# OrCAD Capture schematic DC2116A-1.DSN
size Custom
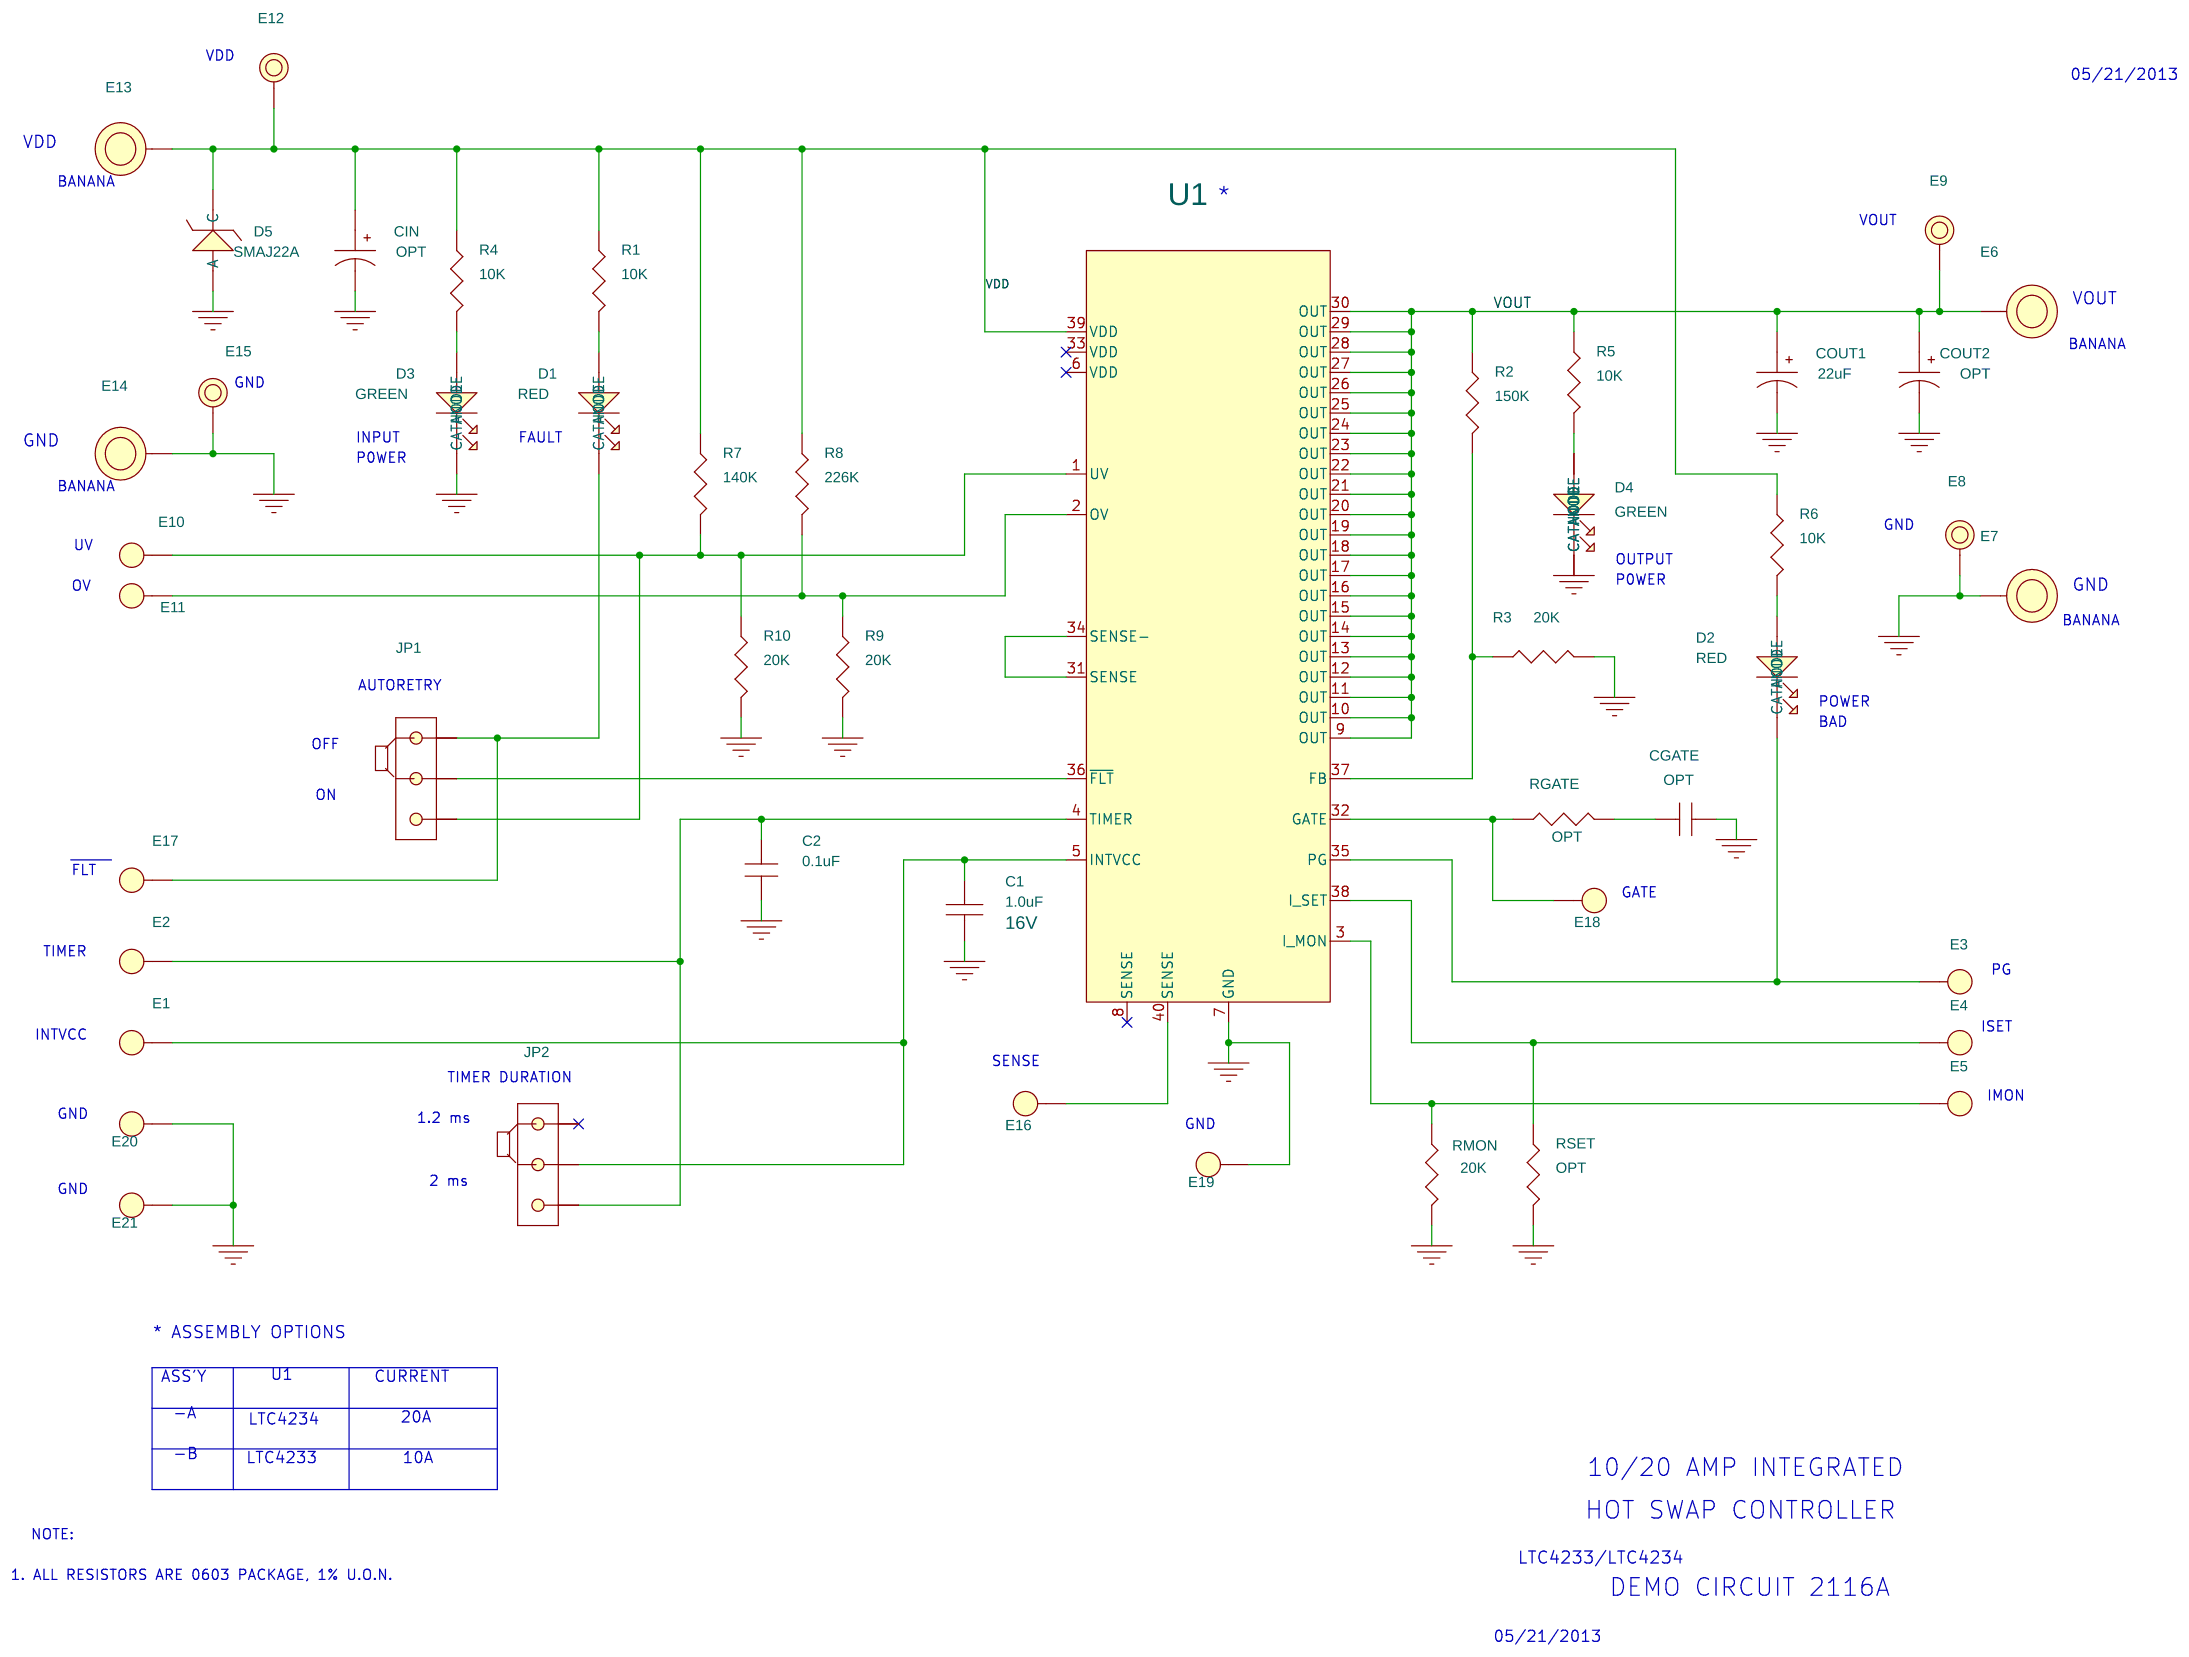
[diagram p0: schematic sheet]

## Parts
C1  1.0uF  [CC0603N]
C2  0.1uF  [CC0603N]
CGATE  OPT  [CC0603N]
CIN  OPT  [CAPTANT7343N]
COUT1  22uF  [CAPTANT7343N]
COUT2  OPT  [CAPTANT7343N]
D1  RED  [WURTH_LED_0805]
D2  RED  [WURTH_LED_0805]
D3  GREEN  [WURTH_LED_0805]
D4  GREEN  [WURTH_LED_0805]
D5  SMAJ22A  [DIODESINC-SMA]
E1  MILL-MAX 2308  [MILLMAX2308]
E2  MILL-MAX 2308  [MILLMAX2308]
E3  MILL-MAX 2308  [MILLMAX2308]
E4  MILL-MAX 2308  [MILLMAX2308]
E5  MILL-MAX 2308  [MILLMAX2308]
E6  BANANA, KEYSTONE-575-4  [KEY-575-4]
E7  BANANA, KEYSTONE-575-4  [KEY-575-4]
E8  MILL MAX 2501  [MILLMAX2501]
E9  MILL MAX 2501  [MILLMAX2501]
E10  MILL-MAX 2308  [MILLMAX2308]
E11  MILL-MAX 2308  [MILLMAX2308]
E12  MILL MAX 2501  [MILLMAX2501]
E13  BANANA, KEYSTONE-575-4  [KEY-575-4]
E14  BANANA, KEYSTONE-575-4  [KEY-575-4]
E15  MILL MAX 2501  [MILLMAX2501]
E16  MILL-MAX 2308  [MILLMAX2308]
E17  MILL-MAX 2308  [MILLMAX2308]
E18  MILL-MAX 2308  [MILLMAX2308]
E19  MILL-MAX 2308  [MILLMAX2308]
E20  MILL-MAX 2308  [MILLMAX2308]
E21  MILL-MAX 2308  [MILLMAX2308]
JP1  3 Pins 2mm Ctrs.  [JP3X1/079]
JP2  3 Pins 2mm Ctrs.  [JP3X1/079]
R1  10K  [CR0805N]
R2  150K  [CR0603N]
R3  20K  [CR0603N]
R4  10K  [CR0805N]
R5  10K  [CR0805N]
R6  10K  [CR0805N]
R7  140K  [CR0603N]
R8  226K  [CR0603N]
R9  20K  [CR0603N]
R10  20K  [CR0603N]
RGATE  OPT  [CR0603N]
RMON  20K  [CR0805N]
RSET  OPT  [CR0805N]
U1  LTC4234CWHH  [LTC-WHH]
XJP1  2mm Ctrs.
XJP2  2mm Ctrs.

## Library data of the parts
C1 = CAP: CAP., 1uF, X7R, 16V, 10%, 0603; CLASS: DISCRETE; Dielectric Type: X7R; Manufacturer: AVX; Manufacturer PN: 0603YC105KAT2A; PART_NUMBER: 150-3384; Package Size: 0603; Rated Voltage: 16V; Tolerance: 10%
C2 = 0.1uF_16V_10%_X7R_0603
CGATE = OPT_0603
CIN COUT2 = CAP_OPT_7343
COUT1 = 22uF_25V_10%_TANT._7343
D1 D2 = LED,RED,_0805,_WURTH
D3 D4 = LED,GREEN,_0805,_WURTH
D5 = DIODE,_TVS,_SMAJ22A,_SMA
E1-E5 E10 E11 E16-E21 = TEST_POINT,_.156,_MILL-MAX_2308
E6 E7 E13 E14 = BANANA,_KEYSTONE-575-4
E8 E9 E12 E15 = TESTPOINT,_.219,_MILL-_MAX_2501
JP1 JP2 = 3_PIN_HEADER_D_.079_SINGLE_ROW
R1 R4-R6 = 10K_5%_1_8W_0805
R2 = 150K_1%_1_10W_0603
R3 R9 R10 = 20K_1%_1_10W_0603
R7 = 140K_1%_1_10W_0603
R8 = 226K_1%_1_10W_0603
RGATE = OPT_0603_v2
RMON = 20K_1%_1_8W_0805
RSET = OPT_0805
U1 = LTC4234
XJP1 XJP2 = SHUNT,_2MM

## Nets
GND: C1.2 C2.2 CGATE.2 CIN.2 COUT1.2 COUT2.2 D3.1(CATHODE) D4.1(CATHODE) D5.2(A) E7.1 E8.1 E14.1 E15.1 E19.1(A) E20.1(A) E21.1(A) R3.2 R9.2 R10.2 RMON.2 RSET.2 U1.7(GND)
VDD: CIN.1 D5.1(C) E12.1 E13.1 R1.1 R4.1 R6.1 R7.1 R8.1 U1.39(VDD)
VOUT: COUT1.1 COUT2.1 E6.1 E9.1 R2.1 R5.1 U1.9(OUT) U1.10(OUT) U1.11(OUT) U1.12(OUT) U1.13(OUT) U1.14(OUT) U1.15(OUT) U1.16(OUT) U1.17(OUT) U1.18(OUT) U1.19(OUT) U1.20(OUT) U1.21(OUT) U1.22(OUT) U1.23(OUT) U1.24(OUT) U1.25(OUT) U1.26(OUT) U1.27(OUT) U1.28(OUT) U1.29(OUT) U1.30(OUT)
N17257135: E10.1(A) JP1.3 R7.2 R10.1 U1.1(UV)
N17258019: D1.2(ANODE) R1.2
N17259450: R2.2 R3.1 U1.37(FB)
N17260317: E18.1(A) RGATE.1 U1.32(GATE)
N17260749: D4.2(ANODE) R5.2
N17266443: CGATE.1 RGATE.2
N17266958: D2.1(CATHODE) E3.1(A) U1.35(PG)
N17267615: E4.1(A) RSET.1 U1.38(I_SET)
N17268383: E5.1(A) RMON.1 U1.3(I_MON)
N17278684: U1.31(SENSE) U1.34(SENSE-)
N17279155: E16.1(A) U1.40(SENSE)
N17280271: C1.1 E1.1(A) JP2.2 U1.5(INTVCC)
N17280398: C2.1 E2.1(A) JP2.3 U1.4(TIMER)
N17281315: E11.1(A) R8.2 R9.1 U1.2(OV)
N17286762: JP1.2 U1.36(~{FLT})
N17287923: D1.1(CATHODE) E17.1(A) JP1.1
N17307750: D3.2(ANODE) R4.2
N17422169: D2.2(ANODE) R6.2

Not connected (* = marked no-connect by the designer): JP2 1*; U1 6(VDD)* 8(SENSE)* 33(VDD)*

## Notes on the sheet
- VDD
- 05/21/2013
- VDD
- BANANA
- *
- VOUT
- VOUT
- BANANA
- GND
- GND
- INPUT
- FAULT
- P0WER
- BANANA
- UV
- GND
- OUTPUT
- OV
- P0WER
- GND
- BANANA
- AUTORETRY
- POWER
- BAD
- OFF
- ON
- FLT
- GATE
- TIMER
- PG
- ISET
- INTVCC
- SENSE
- TIMER DURATION
- IMON
- GND
- 1.2 ms
- GND
- GND
- 2 ms
- * ASSEMBLY OPTIONS
- ASS'Y
- U1
- CURRENT
- -A
- LTC4234
- 20A
- -B
- LTC4233
- 10A
- 10/20 AMP INTEGRATED
- HOT SWAP CONTROLLER
- NOTE:
- 1. ALL RESISTORS ARE 0603 PACKAGE, 1% U.O.N.
- LTC4233/LTC4234
- DEMO CIRCUIT 2116A
- 05/21/2013
